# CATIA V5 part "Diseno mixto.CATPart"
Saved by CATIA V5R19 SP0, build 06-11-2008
Part number: Part2
Bounding box of the stored display mesh (mm): x -127.738 to 51.775, y -51.797 to 232.117, z -12.765 to 59.925
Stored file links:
  G:\Prácticas\0068\68_v5r19\Diseno mixto.CATPart
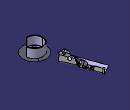
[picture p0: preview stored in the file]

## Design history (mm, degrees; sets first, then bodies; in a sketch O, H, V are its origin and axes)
Body1 (main body)
  Set1
    DatumSurface1
  ThickSurface1: Surface DatumSurface1, BotOffset 0, TopOffset 1
Body2
  Set2
    Plane1: type Offset, Offset 44, RefPlane xy-plane
    DatumSurface2
  Sketch1 on Plane1, origin (0, 0, 44), H (1, 0, 0), V (0, 1, 0)
    circle A1 centre (0, 0) radius 37.202
  Pad1: profile Sketch1, direction (0, 0, 1), up to DatumSurface2
  Fillet1: radius 2, on edge [face of Pad1 from Sketch1.A1 | face of Pad1]
  Sketch2 on start face of Pad1, origin (0, 0, 44), H (1, 0, 0), V (0, 1, 0)
    offset circle E2 centre (0, 0) radius 34.6371 from start face of Pad1
  Pocket1: profile Sketch2, direction (0, 0, -1), up to face of Pad1, offset -3
  Sketch3 on xy-plane, origin (0, 0, 0), H (1, 0, 0), V (0, 1, 0)
    line L1 (0, 0) -> (46.7763, 0)
    line L2 (46.7763, 0) -> (46.7763, -45.1243)
    line L3 (46.7763, -45.1243) -> (0, -45.1243)
    point P3 (0, -45.1243)
    line L4 (0, -45.1243) -> (0, 0)
    horizontal: L1 H, L3 H
    vertical: L2 V, L4 V
    coincidence: P3 V
  Pocket2: profile Sketch3, direction (0, 0, 1), through (limit type 3), opposite side through (limit type 3)
  Fillet2: radius 2, on edge [end face of Pocket1 | face of Pocket1]
  Fillet3: radius 0.5, on edge [end face of Pocket1 | face of Pocket1 from Sketch2.E2]; edge [face of Pocket1 | face of Pocket1]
